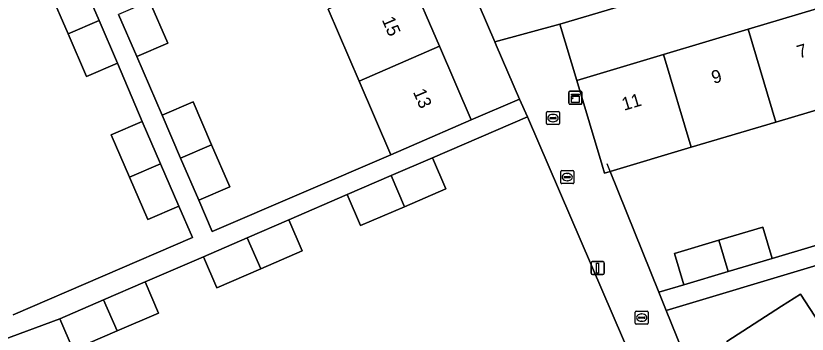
# Model space of a CAD drawing. Extents: x 159352 to 160617, y 385888 to 387323.
# Drawn here: x 159688.2 to 159749, y 386357 to 386381.5 of the extents above; entities that cross this region are included whole.
import ezdxf

# ---------------------------------------------------------------- set-up
doc = ezdxf.new("R2010")
doc.units = 0
for name, color, linetype in [('IMGEO_Erf', 7, 'Continuous'), ('IMGEO_Kast', 7, 'Continuous'), ('IMGEO_Kolk', 7, 'Continuous'), ('IMGEO_Lichtmast', 7, 'Continuous'), ('IMGEO_Muur', 7, 'Continuous'), ('IMGEO_Pand', 7, 'Continuous'), ('IMGEO_Pand_nummerreeks', 7, 'Continuous'), ('IMGEO_Rioolput', 7, 'Continuous'), ('IMGEO_Voetpad_open', 7, 'Continuous')]:
    doc.layers.add(name, color=color, linetype=linetype)

msp = doc.modelspace()

# ---------------------------------------------------------------- linework, layer by layer
at = {"layer": 'IMGEO_Erf'}
msp.add_lwpolyline([(159703.042, 386430.628), (159699.301, 386429.028), (159701.741, 386423.368), (159704.122, 386417.845), (159706.504, 386412.322), (159708.885, 386406.798), (159711.267, 386401.274), (159713.648, 386395.751), (159716.029, 386390.228), (159718.411, 386384.704), (159720.792, 386379.18), (159723.232, 386373.521), (159726.944, 386375.119), (159725.152, 386379.28), (159725.05, 386379.518)], close=True, dxfattribs=at)
for points in [[(159770.115, 386392.78), (159730.028, 386380.895), (159731.34, 386376.558), (159737.998, 386378.548), (159744.511, 386380.494), (159751.025, 386382.441), (159757.538, 386384.388), (159764.051, 386386.334)], [(159688.018, 386358.522), (159701.797, 386364.467), (159700.758, 386366.874), (159698.383, 386365.85), (159696.973, 386369.118), (159695.569, 386372.372), (159697.944, 386373.396), (159696.039, 386377.895), (159693.664, 386376.871), (159692.254, 386380.138), (159690.85, 386383.393), (159693.225, 386384.417), (159691.32, 386388.915), (159688.945, 386387.891), (159687.535, 386391.16)], [(159698.516, 386382.651), (159699.907, 386379.426), (159697.523, 386378.398), (159699.472, 386373.873), (159701.856, 386374.901), (159703.278, 386371.605), (159704.67, 386368.379), (159702.286, 386367.351), (159703.332, 386364.927), (159717.049, 386370.84), (159714.607, 386376.505), (159712.225, 386382.029)], [(159753.156, 386375.302), (159746.642, 386373.355), (159740.129, 386371.409), (159733.894, 386369.547), (159737.642, 386360.262), (159739.565, 386360.835), (159738.845, 386363.253), (159742.259, 386364.27), (159745.631, 386365.274), (159746.351, 386362.856), (159752.592, 386364.728)], [(159727.536, 386373.743), (159720.249, 386370.605), (159721.28, 386368.219), (159718.093, 386366.842), (159714.716, 386365.384), (159713.685, 386367.77), (159709.209, 386365.826), (159710.24, 386363.44), (159707.052, 386362.063), (159703.676, 386360.605), (159702.645, 386362.991), (159698.168, 386361.048), (159699.199, 386358.662), (159696.011, 386357.285), (159692.635, 386355.827), (159691.604, 386358.213), (159687.18, 386356.583), (159688.233, 386354.242), (159684.894, 386352.739), (159683.84, 386355.08), (159678.391, 386352.741), (159688.233, 386329.814)], [(159737.386, 386350.867), (159727.536, 386373.743)], [(159793.797, 386316.542), (159791.022, 386320.752), (159788.643, 386319.195), (159786.671, 386322.188), (159784.762, 386325.083), (159786.901, 386326.492), (159784.156, 386330.214), (159781.898, 386328.735), (159779.953, 386331.706), (159777.919, 386334.812), (159780.178, 386336.291), (159777.843, 386339.993), (159775.585, 386338.514), (159771.606, 386344.591), (159773.865, 386346.07), (159764.875, 386359.296), (159762.584, 386357.757), (159758.495, 386363.843), (159760.786, 386365.382), (159760.635, 386365.607), (159738.213, 386358.849), (159740.771, 386352.514), (159758.089, 386325.63), (159772.624, 386303.066)], [(159768.209, 386317.23), (159765.052, 386322.12), (159761.895, 386327.009), (159758.737, 386331.898), (159755.58, 386336.788), (159752.423, 386341.677), (159749.266, 386346.566), (159746.109, 386351.455), (159742.87, 386356.47), (159747.075, 386359.177), (159748.538, 386360.118), (159751.777, 386355.101), (159754.933, 386350.211), (159758.089, 386345.322), (159761.245, 386340.432), (159764.402, 386335.542), (159767.253, 386337.404), (159770.438, 386332.472), (159773.562, 386327.616), (159770.715, 386325.763), (159773.871, 386320.873), (159777.027, 386315.983)]]:
    msp.add_lwpolyline(points, dxfattribs=at)
at = {"layer": 'IMGEO_Kast'}
for p, q in [((159730.731, 386374.796), (159730.731, 386375.637)), ((159730.731, 386375.637), (159730.731, 386374.796)), ((159730.806, 386375.721), (159731.647, 386375.721)), ((159731.647, 386375.721), (159730.806, 386375.721)), ((159731.731, 386375.646), (159731.731, 386374.805)), ((159731.731, 386374.805), (159731.731, 386375.646)), ((159731.656, 386374.721), (159730.815, 386374.721)), ((159730.815, 386374.721), (159731.656, 386374.721))]:
    msp.add_line(p, q, dxfattribs=at)
for points in [[(159730.926, 386375.511), (159731.526, 386375.511), (159731.526, 386375.426), (159730.926, 386375.426), (159730.926, 386375.511)], [(159730.926, 386375.336), (159731.526, 386375.336), (159731.526, 386374.847), (159730.926, 386374.847), (159730.926, 386375.336)]]:
    msp.add_lwpolyline(points, dxfattribs=at)
msp.add_circle((159731.01, 386375.185), 0.0377, dxfattribs=at)
for centre, start, end in [((159730.809, 386375.643), 92.4484, 184.28452), ((159730.809, 386375.643), 92.4484, 184.28452), ((159731.653, 386375.643), 2.4484, 94.28452), ((159731.653, 386375.643), 2.4484, 94.28452), ((159730.809, 386374.799), 182.4484, 274.28452), ((159730.809, 386374.799), 182.4484, 274.28452), ((159731.653, 386374.799), 272.4484, 4.28452), ((159731.653, 386374.799), 272.4484, 4.28452)]:
    msp.add_arc(centre, 0.0779, start, end, dxfattribs=at)
at = {"layer": 'IMGEO_Kolk'}
for p, q in [((159729.007, 386373.231), (159729.007, 386374.083)), ((159729.082, 386374.157), (159729.934, 386374.157)), ((159730.008, 386374.083), (159730.008, 386373.231)), ((159729.266, 386373.651), (159729.266, 386373.663)), ((159729.704, 386373.614), (159729.306, 386373.614)), ((159729.309, 386373.7), (159729.707, 386373.7)), ((159729.495, 386373.937), (159729.52, 386373.937)), ((159729.75, 386373.663), (159729.75, 386373.651)), ((159729.934, 386373.157), (159729.082, 386373.157)), ((159729.518, 386373.377), (159729.493, 386373.377)), ((159735.827, 386357.884), (159735.827, 386358.736)), ((159735.902, 386358.81), (159736.754, 386358.81)), ((159736.086, 386358.304), (159736.086, 386358.316)), ((159736.524, 386358.267), (159736.126, 386358.267)), ((159736.129, 386358.353), (159736.527, 386358.353)), ((159736.315, 386358.59), (159736.34, 386358.59)), ((159736.57, 386358.316), (159736.57, 386358.304)), ((159736.828, 386358.736), (159736.828, 386357.884)), ((159736.754, 386357.81), (159735.902, 386357.81)), ((159736.338, 386358.03), (159736.313, 386358.03))]:
    msp.add_line(p, q, dxfattribs=at)
for points in [[(159729.007, 386373.231), (159729.007, 386374.083)], [(159729.082, 386374.157), (159729.934, 386374.157)], [(159730.008, 386374.083), (159730.008, 386373.231)], [(159729.934, 386373.157), (159729.082, 386373.157)], [(159735.827, 386357.884), (159735.827, 386358.736)], [(159735.902, 386358.81), (159736.754, 386358.81)], [(159736.828, 386358.736), (159736.828, 386357.884)], [(159736.754, 386357.81), (159735.902, 386357.81)]]:
    msp.add_lwpolyline(points, dxfattribs=at)
for centre, radius, start, end in [((159729.084, 386374.081), 0.0765, 91.55205, 178.44795), ((159729.084, 386374.081), 0.0765, 91.55205, 178.44795), ((159729.932, 386374.081), 0.0765, 1.55205, 88.44795), ((159729.932, 386374.081), 0.0765, 1.55205, 88.44795), ((159729.306, 386373.66), 0.0403, 85.87752, 175.75265), ((159729.303, 386373.65), 0.0366, 178.93798, 274.71019), ((159729.707, 386373.657), 0.043, 264.86636, 352.45326), ((159729.711, 386373.662), 0.0386, 1.73085, 96.63898), ((159729.084, 386373.233), 0.0765, 181.55205, 268.44795), ((159729.084, 386373.233), 0.0765, 181.55205, 268.44795), ((159729.932, 386373.233), 0.0765, 271.55205, 358.44795), ((159729.932, 386373.233), 0.0765, 271.55205, 358.44795), ((159735.904, 386358.734), 0.0765, 91.55205, 178.44795), ((159735.904, 386358.734), 0.0765, 91.55205, 178.44795), ((159736.126, 386358.313), 0.0403, 85.87752, 175.75265), ((159736.123, 386358.303), 0.0366, 178.93798, 274.71019), ((159736.527, 386358.31), 0.043, 264.86636, 352.45326), ((159736.531, 386358.315), 0.0386, 1.73085, 96.63898), ((159736.752, 386358.734), 0.0765, 1.55205, 88.44795), ((159736.752, 386358.734), 0.0765, 1.55205, 88.44795), ((159735.904, 386357.886), 0.0765, 181.55205, 268.44795), ((159735.904, 386357.886), 0.0765, 181.55205, 268.44795), ((159736.752, 386357.886), 0.0765, 271.55205, 358.44795), ((159736.752, 386357.886), 0.0765, 271.55205, 358.44795)]:
    msp.add_arc(centre, radius, start, end, dxfattribs=at)
for centre, major_axis, ratio, start_param, end_param in [((159729.494, 386373.657), (-0.387, 0.002), 0.722429, 4.712389, 7.853982), ((159729.519, 386373.657), (-0.39, 0.002), 0.717154, 1.570796, 4.712389), ((159736.314, 386358.31), (-0.387, 0.002), 0.722429, 4.712389, 7.853982), ((159736.339, 386358.31), (-0.39, 0.002), 0.717154, 1.570796, 4.712389)]:
    msp.add_ellipse(centre, major_axis=major_axis, ratio=ratio, start_param=start_param, end_param=end_param, dxfattribs=at)
at = {"layer": 'IMGEO_Lichtmast'}
for p, q in [((159732.443, 386361.715), (159732.443, 386362.515)), ((159732.443, 386362.515), (159732.443, 386361.715)), ((159732.543, 386362.615), (159733.333, 386362.615)), ((159733.333, 386362.615), (159732.543, 386362.615)), ((159733.433, 386362.515), (159733.433, 386361.715)), ((159733.433, 386361.715), (159733.433, 386362.515)), ((159733.333, 386361.615), (159732.543, 386361.615)), ((159732.543, 386361.615), (159733.333, 386361.615))]:
    msp.add_line(p, q, dxfattribs=at)
msp.add_lwpolyline([(159732.863, 386362.49), (159733.013, 386362.49), (159733.013, 386361.74), (159732.863, 386361.74), (159732.863, 386362.49)], dxfattribs=at)
for centre, start, end in [((159732.543, 386362.515), 90, 180), ((159732.543, 386362.515), 90, 180), ((159733.333, 386362.515), 0, 90), ((159733.333, 386362.515), 360, 90), ((159732.543, 386361.715), 180, 270), ((159732.543, 386361.715), 180, 270), ((159733.333, 386361.715), 270, 0), ((159733.333, 386361.715), 270, 0)]:
    msp.add_arc(centre, 0.1, start, end, dxfattribs=at)
at = {"layer": 'IMGEO_Muur'}
msp.add_lwpolyline([(159733.649, 386370.153), (159737.642, 386360.262)], dxfattribs=at)
at = {"layer": 'IMGEO_Pand'}
for points in [[(159693.225, 386384.417), (159690.85, 386383.393), (159692.254, 386380.138), (159694.628, 386381.165)], [(159712.225, 386382.029), (159714.607, 386376.505), (159720.792, 386379.18), (159718.411, 386384.704)], [(159697.523, 386378.398), (159699.907, 386379.426), (159698.516, 386382.651), (159696.133, 386381.62)], [(159746.642, 386373.355), (159753.156, 386375.302), (159751.025, 386382.441), (159744.511, 386380.494)], [(159693.664, 386376.871), (159696.039, 386377.895), (159694.628, 386381.165), (159692.254, 386380.138)], [(159744.511, 386380.494), (159737.998, 386378.548), (159740.129, 386371.409), (159746.642, 386373.355)], [(159714.607, 386376.505), (159717.049, 386370.84), (159718.645, 386371.532), (159723.232, 386373.521), (159720.792, 386379.18)], [(159737.998, 386378.548), (159731.34, 386376.558), (159733.286, 386370.045), (159733.472, 386369.421), (159733.894, 386369.547), (159740.129, 386371.409)], [(159701.856, 386374.901), (159699.472, 386373.873), (159700.895, 386370.575), (159703.278, 386371.605)], [(159697.944, 386373.396), (159695.569, 386372.372), (159696.973, 386369.118), (159699.346, 386370.146)], [(159702.286, 386367.351), (159704.67, 386368.379), (159703.278, 386371.605), (159700.895, 386370.575)], [(159718.093, 386366.842), (159721.28, 386368.219), (159720.249, 386370.605), (159717.062, 386369.229)], [(159698.383, 386365.85), (159700.758, 386366.874), (159699.346, 386370.146), (159696.973, 386369.118)], [(159717.062, 386369.229), (159713.685, 386367.77), (159714.716, 386365.384), (159718.093, 386366.842)], [(159710.24, 386363.44), (159709.209, 386365.826), (159706.021, 386364.449), (159707.052, 386362.063)], [(159742.98, 386361.852), (159746.351, 386362.856), (159745.631, 386365.274), (159742.259, 386364.27)], [(159702.645, 386362.991), (159703.676, 386360.605), (159707.052, 386362.063), (159706.021, 386364.449)], [(159742.259, 386364.27), (159738.845, 386363.253), (159739.565, 386360.835), (159742.98, 386361.852)], [(159699.199, 386358.662), (159698.168, 386361.048), (159694.981, 386359.671), (159696.011, 386357.285)], [(159751.777, 386355.101), (159748.538, 386360.118), (159747.075, 386359.177), (159742.87, 386356.47), (159746.109, 386351.455)], [(159691.604, 386358.213), (159692.635, 386355.827), (159696.011, 386357.285), (159694.981, 386359.671)]]:
    msp.add_lwpolyline(points, close=True, dxfattribs=at)
at = {"layer": 'IMGEO_Rioolput'}
for p, q in [((159730.1, 386368.689), (159730.1, 386369.541)), ((159730.175, 386369.615), (159731.027, 386369.615)), ((159730.588, 386369.395), (159730.613, 386369.395)), ((159731.101, 386369.541), (159731.101, 386368.689)), ((159731.027, 386368.615), (159730.175, 386368.615)), ((159730.359, 386369.109), (159730.359, 386369.121)), ((159730.797, 386369.072), (159730.399, 386369.072)), ((159730.402, 386369.158), (159730.8, 386369.158)), ((159730.611, 386368.835), (159730.586, 386368.835)), ((159730.843, 386369.121), (159730.843, 386369.109))]:
    msp.add_line(p, q, dxfattribs=at)
for points in [[(159730.1, 386368.689), (159730.1, 386369.541)], [(159730.175, 386369.615), (159731.027, 386369.615)], [(159731.101, 386369.541), (159731.101, 386368.689)], [(159731.027, 386368.615), (159730.175, 386368.615)]]:
    msp.add_lwpolyline(points, dxfattribs=at)
for centre, radius, start, end in [((159730.177, 386369.539), 0.0765, 91.55205, 178.44795), ((159730.177, 386369.539), 0.0765, 91.55205, 178.44795), ((159731.025, 386369.539), 0.0765, 1.55205, 88.44795), ((159731.025, 386369.539), 0.0765, 1.55205, 88.44795), ((159730.177, 386368.691), 0.0765, 181.55205, 268.44795), ((159730.177, 386368.691), 0.0765, 181.55205, 268.44795), ((159730.399, 386369.118), 0.0403, 85.87752, 175.75265), ((159730.396, 386369.108), 0.0366, 178.93798, 274.71019), ((159730.8, 386369.115), 0.043, 264.86636, 352.45326), ((159730.804, 386369.12), 0.0386, 1.73085, 96.63898), ((159731.025, 386368.691), 0.0765, 271.55205, 358.44795), ((159731.025, 386368.691), 0.0765, 271.55205, 358.44795)]:
    msp.add_arc(centre, radius, start, end, dxfattribs=at)
for centre, major_axis, ratio, start_param, end_param in [((159730.587, 386369.115), (-0.387, 0.002), 0.722429, 4.712389, 7.853982), ((159730.612, 386369.115), (-0.39, 0.002), 0.717154, 1.570796, 4.712389)]:
    msp.add_ellipse(centre, major_axis=major_axis, ratio=ratio, start_param=start_param, end_param=end_param, dxfattribs=at)
at = {"layer": 'IMGEO_Voetpad_open'}
for points in [[(159696.755, 386440.037), (159700.029, 386435.875), (159700.074, 386435.88), (159703.042, 386430.628), (159725.05, 386379.518), (159730.028, 386380.895), (159770.115, 386392.78)], [(159686.601, 386399.935), (159688.506, 386395.437), (159689.908, 386392.187), (159691.32, 386388.915), (159693.225, 386384.417), (159694.628, 386381.165), (159696.039, 386377.895), (159697.944, 386373.396), (159699.346, 386370.146), (159700.758, 386366.874), (159701.797, 386364.467), (159688.018, 386358.522)], [(159687.18, 386356.583), (159691.604, 386358.213), (159694.981, 386359.671), (159698.168, 386361.048), (159702.645, 386362.991), (159706.021, 386364.449), (159709.209, 386365.826), (159713.685, 386367.77), (159717.062, 386369.229), (159720.249, 386370.605), (159727.536, 386373.743), (159726.944, 386375.119), (159723.232, 386373.521), (159718.645, 386371.532), (159717.049, 386370.84), (159703.332, 386364.927), (159702.286, 386367.351), (159700.895, 386370.575), (159699.472, 386373.873), (159697.523, 386378.398), (159696.133, 386381.62)], [(159740.771, 386352.514), (159738.213, 386358.849), (159737.642, 386360.262), (159733.894, 386369.547), (159733.472, 386369.421), (159733.286, 386370.045), (159731.34, 386376.558), (159730.028, 386380.895), (159725.05, 386379.518), (159725.152, 386379.28), (159726.944, 386375.119), (159727.536, 386373.743), (159737.386, 386350.867), (159737.444, 386350.836), (159740.289, 386343.768), (159746.155, 386334.72)], [(159752.592, 386364.728), (159746.351, 386362.856), (159742.98, 386361.852), (159739.565, 386360.835), (159737.642, 386360.262), (159738.213, 386358.849), (159760.635, 386365.607)]]:
    msp.add_lwpolyline(points, dxfattribs=at)

# ---------------------------------------------------------------- texts
at = {"layer": 'IMGEO_Pand_nummerreeks'}
for s, rotation, p in [('15', 293.32256, (159716.339, 386381.224)), ('7', 16.63994, (159748.419, 386378.239)), ('9', 16.63869, (159741.857, 386376.278)), ('13', 293.32256, (159718.732, 386375.673)), ('11', 16.63869, (159734.964, 386374.218))]:
    msp.add_text(s, height=1, rotation=rotation, dxfattribs=at).set_placement(p)

doc.saveas('drawing.dxf')
